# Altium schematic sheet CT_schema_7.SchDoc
size 287 x 160 mm
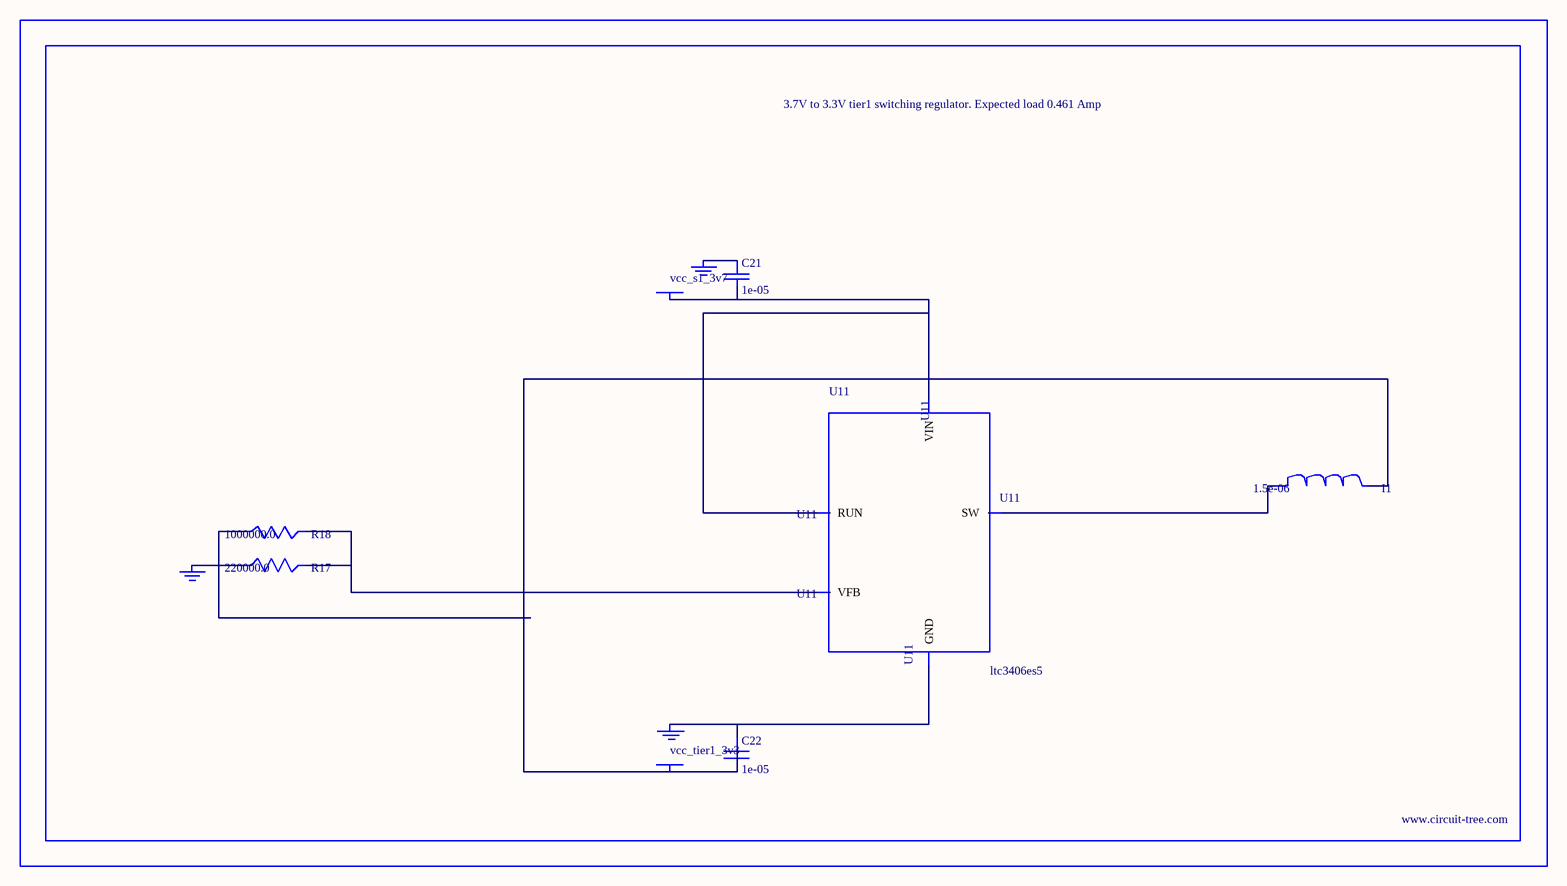
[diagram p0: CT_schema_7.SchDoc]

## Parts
BORDER6  (no value)
C21  1e-05  [C0805]
C22  1e-05  [C0805]
GND_INSTANCE_6_0  (no value)
GND_INSTANCE_6_1  (no value)
GND_INSTANCE_6_2  (no value)
I1  1.5e-06  [L0806]
POWER_INSTANCE_6_0  vcc_tier1_3v3
POWER_INSTANCE_6_1  vcc_s1_3v7
R17  220000.0  [R0603]
R18  1000000.0  [R0603]
U11  ltc3406es5  [TSOT-23-5]

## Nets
NetC21_1: C21.1 GND_INSTANCE_6_1.0(GND)
NetC21_2: C21.2 POWER_INSTANCE_6_1.0(PWR) U11.1(RUN) U11.4(VIN)
NetC22_1: C22.1 GND_INSTANCE_6_0.0(GND) U11.2(GND)
NetC22_2: C22.2 I1.2 POWER_INSTANCE_6_0.0(PWR) R18.1
NetGND_INSTANCE_6_2_0: GND_INSTANCE_6_2.0(GND) R17.1
NetI1_1: I1.1 U11.3(SW)
NetR17_2: R17.2 R18.2 U11.5(VFB)

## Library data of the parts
BORDER6 = BORDER_PAGE6
C21 C22 = C0805C106K8RACTU
GND_INSTANCE_6_0-GND_INSTANCE_6_2 = GND
I1 = L0806C1R5MDWIT
POWER_INSTANCE_6_0 POWER_INSTANCE_6_1 = PWR
R17 = RC0603JR-07220KL
R18 = RC0603JR-071ML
